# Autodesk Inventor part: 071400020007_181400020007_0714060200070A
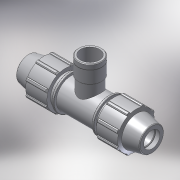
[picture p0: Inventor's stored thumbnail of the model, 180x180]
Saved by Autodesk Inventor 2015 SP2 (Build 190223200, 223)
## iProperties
Created: 2017-02
Part Number: 071400020007_181400020007_0714060200070A
Material: PVC-Piping
Description: PLASSON TEE WITH THREADED FEMALE OFFTAKE 20-3/4"-20
Document SubType Name: Modeling
Designer: KIM
Mass: 92.6774 g
Surface Area: 199.44 cm^2
Volume: 66.1981 cm^3
Density: 1.4 g/cm^3
Appearance: Smooth - White
Author: KIM
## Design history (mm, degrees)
derived "07140.ipt"
feature "Solid1::07140.ipt"
feature "Solid2::07140.ipt"
tag "TaggingFeature1"
body "Solid1"
other parameters: "d4" = 6, "d5" = 17.28, "d7" = 48, "d11" = 2.4, "d13" = 120 deg, "d15" = 12 deg, "d16" = 41.76, "d18" = 1, "d19" = 35 deg, "d20" = 17.5 deg, "d21" = 44.64, "d23" = 0, "d25" = 360 deg, "d27" = 0.96, "d33" = 0.4, "d42" = 25.92, "d43" = 1.44, "d46" = 0.6, "d68" = 4.32, "d72" = 45, "d76" = 24.117, "d80" = 0.72351, "d91" = 36, "d93" = 56, "d95" = 18, "d112" = 19, "d115" = 30.14625, "d116" = 135 deg, "d117" = 27.73455, "d118" = 144, "d119" = 18, "d121" = 0, "d122" = 18, "d124" = 0, "d128" = 0, "d129" = 2, "d130" = 5.7, "d131" = 0.3, "d132" = 0.3, "d133" = 30.14625, "E_" = 48, "A_" = 45, "l_" = 56, "l_2" = 19, "Rp_" = 24.117, "H_" = 144
